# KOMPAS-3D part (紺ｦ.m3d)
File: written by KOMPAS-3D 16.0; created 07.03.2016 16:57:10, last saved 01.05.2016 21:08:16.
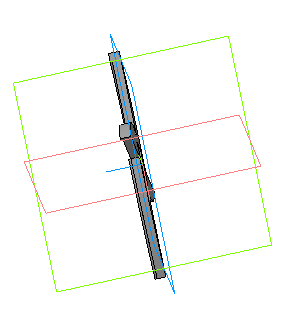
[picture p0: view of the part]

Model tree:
1. Эскиз:1
2. Операция выдавливания:1
     Расстояние 1 = 2
3. Эскиз:2
4. Операция выдавливания:2
     Расстояние 1 = 0.5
